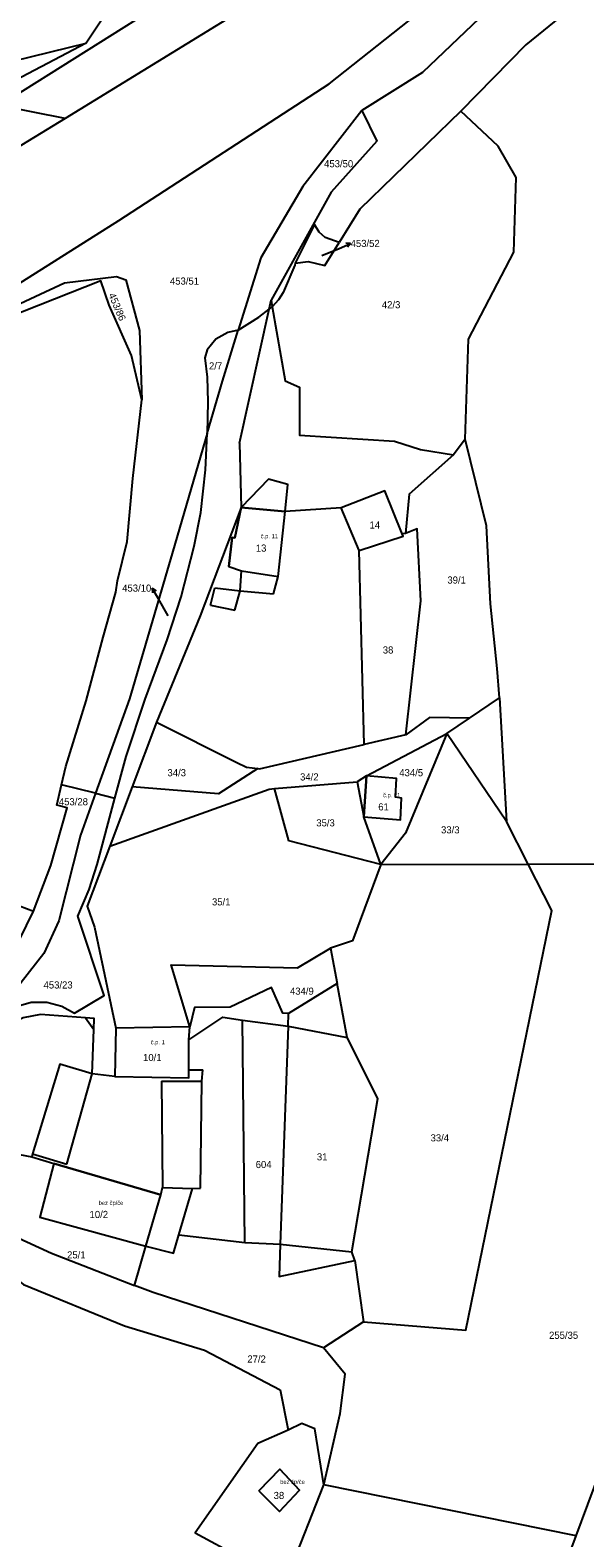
# Model space of a CAD drawing. Extents: x -882150 to -879379, y -1022570 to -1019819.
# Drawn here: x -880489.6 to -880356.9, y -1021365.7 to -1021005.3 of the extents above; entities that cross this region are included whole.
import ezdxf

# ---------------------------------------------------------------- set-up
doc = ezdxf.new("R2010")
doc.units = 0
for name, color, linetype in [('Definiční body', 7, 'Continuous'), ('Hranice parcel', 7, 'Continuous'), ('Parcelní čísla', 7, 'Continuous'), ('Polygon budovy', 7, 'Continuous'), ('Pop  PČ popisy', 7, 'Continuous'), ('Vnitřní kresba', 7, 'Continuous')]:
    doc.layers.add(name, color=color, linetype=linetype)

msp = doc.modelspace()

# ---------------------------------------------------------------- linework, layer by layer
at = {"layer": 'Hranice parcel'}
for p, q in [((-880476.16, -1021008.4), (-880502.57, -1021022.27)), ((-880481.22, -1021026.44), (-880495.95, -1021035.41)), ((-880431.99, -1021069.84), (-880431.71, -1021071.41)), ((-880385.56, -1021103.08), (-880388.33, -1021106.79)), ((-880415.23, -1021119.47), (-880428.61, -1021120.37)), ((-880410.9, -1021129.7), (-880415.23, -1021119.47)), ((-880399.83, -1021125.58), (-880400.61, -1021125.73)), ((-880409.7, -1021176.06), (-880410.9, -1021129.7)), ((-880459.41, -1021170.76), (-880465.21, -1021186.18)), ((-880389.96, -1021173.43), (-880384.55, -1021169.77)), ((-880399.71, -1021173.73), (-880409.7, -1021176.06)), ((-880409.15, -1021183.56), (-880389.96, -1021173.43)), ((-880431.14, -1021186.58), (-880411.38, -1021184.98)), ((-880409.15, -1021183.56), (-880411.38, -1021184.98)), ((-880411.38, -1021184.98), (-880409.82, -1021193.33)), ((-880473.96, -1021187.71), (-880482.08, -1021185.73)), ((-880473.96, -1021187.71), (-880469.31, -1021188.85)), ((-880465.21, -1021186.18), (-880470.56, -1021200.38)), ((-880427.72, -1021199.1), (-880431.14, -1021186.58)), ((-880405.75, -1021204.73), (-880409.82, -1021193.33)), ((-880405.75, -1021204.73), (-880427.72, -1021199.1)), ((-880405.75, -1021204.73), (-880370.46, -1021204.66)), ((-880370.46, -1021204.66), (-880352.16, -1021204.62)), ((-880497.26, -1021212.75), (-880488.78, -1021215.92)), ((-880417.76, -1021224.73), (-880416.19, -1021233.16)), ((-880416.19, -1021233.16), (-880427.78, -1021240.38)), ((-880438.79, -1021241.92), (-880427.85, -1021243.42)), ((-880427.85, -1021243.42), (-880427.78, -1021240.38)), ((-880469.09, -1021243.89), (-880469.32, -1021255.45)), ((-880451.42, -1021243.56), (-880469.09, -1021243.89)), ((-880469.32, -1021255.45), (-880474.8, -1021254.79)), ((-880496.75, -1021273.23), (-880489.23, -1021274.65)), ((-880464.66, -1021305.36), (-880461.94, -1021295.99)), ((-880411.95, -1021299.44), (-880409.86, -1021314.06)), ((-880409.86, -1021314.06), (-880419.42, -1021320.33)), ((-880428.51, -1021376.32), (-880419.38, -1021353.05)), ((-880359.04, -1021365.24), (-880419.38, -1021353.05))]:
    msp.add_line(p, q, dxfattribs=at)
for points in [[(-880199.05, -1020918.85), (-880200.75, -1020917.75), (-880202.77, -1020917.97), (-880233.19, -1020931.27), (-880251.05, -1020933.81), (-880268.87, -1020944.34), (-880277.99, -1020951.78), (-880283.59, -1020955.76), (-880289.65, -1020959.07), (-880309.25, -1020967.57), (-880323.7, -1020975.72), (-880346.68, -1020990.73), (-880361.3, -1021000.94), (-880371.02, -1021008.81), (-880386.57, -1021024.64)], [(-880309.24, -1020922.47), (-880346.3, -1020941.23), (-880393.91, -1020972.78), (-880481.22, -1021026.44)], [(-880469, -1020965.35), (-880470.29, -1020974.83), (-880471.2, -1020987.07), (-880471.46, -1020993.13), (-880470.95, -1020998.81), (-880470.95, -1021000.53), (-880476.16, -1021008.4)], [(-880574.71, -1021116.82), (-880511.95, -1021078.31), (-880468.39, -1021050.82), (-880418.11, -1021018.15), (-880374.5, -1020983.56)], [(-880374.5, -1020983.56), (-880382.21, -1021002.48), (-880395.74, -1021015.43), (-880410.24, -1021024.49)], [(-880511.24, -1021020.61), (-880502.88, -1021016.62), (-880493.44, -1021012.65), (-880476.16, -1021008.4)], [(-880481.22, -1021026.44), (-880497.01, -1021023.34), (-880502.57, -1021022.27)], [(-880410.24, -1021024.49), (-880424.37, -1021042.64), (-880434.46, -1021059.73), (-880439.82, -1021077.01)], [(-880410.24, -1021024.49), (-880406.66, -1021031.86), (-880417.64, -1021044.05), (-880431.99, -1021069.84)], [(-880386.57, -1021024.64), (-880410.77, -1021048.05), (-880415.69, -1021056.05)], [(-880385.56, -1021103.08), (-880384.77, -1021079.15), (-880373.92, -1021058.36), (-880373.35, -1021040.51), (-880377.69, -1021033.04), (-880386.57, -1021024.64)], [(-880415.69, -1021056.05), (-880419.02, -1021054.89), (-880420.51, -1021053.56), (-880421.57, -1021051.74), (-880426.2, -1021060.98)], [(-880426.2, -1021060.98), (-880423.12, -1021060.62), (-880419.08, -1021061.56), (-880415.69, -1021056.05)], [(-880426.2, -1021060.98), (-880426.26, -1021061.51), (-880429.07, -1021067.97), (-880430.23, -1021069.76), (-880431.71, -1021071.41)], [(-880519.8, -1021083.58), (-880502.52, -1021075.49), (-880481.4, -1021065.7), (-880468.96, -1021064.18), (-880466.73, -1021064.99), (-880463.43, -1021077.08), (-880462.9, -1021093.7)], [(-880462.9, -1021093.7), (-880465.35, -1021083.05), (-880470.69, -1021071.03), (-880472.67, -1021065.21), (-880498.73, -1021075.48), (-880519.8, -1021083.58)], [(-880439.82, -1021077.01), (-880434.91, -1021073.92), (-880432.47, -1021072), (-880431.71, -1021071.41)], [(-880431.71, -1021071.41), (-880428.58, -1021089.14), (-880425.15, -1021090.65), (-880425.18, -1021102.13), (-880402.46, -1021103.56), (-880396.21, -1021105.53), (-880388.33, -1021106.79)], [(-880439.82, -1021077.01), (-880442.34, -1021077.55), (-880445.16, -1021079.15), (-880447.28, -1021081.75), (-880447.85, -1021083.64), (-880447.23, -1021088.28), (-880447.11, -1021094.15), (-880447.26, -1021101.73)], [(-880447.26, -1021101.73), (-880443.6, -1021089.17), (-880439.82, -1021077.01)], [(-880482.08, -1021185.73), (-880481.03, -1021181.33), (-880476.2, -1021165.62), (-880472.17, -1021150.37), (-880469.07, -1021139.61), (-880468.72, -1021136.95), (-880466.42, -1021127.54), (-880465.02, -1021112.47), (-880462.9, -1021093.7)], [(-880447.26, -1021101.73), (-880456.01, -1021131.75), (-880465.87, -1021165.12), (-880473.96, -1021187.71)], [(-880469.31, -1021188.85), (-880466.62, -1021178.9), (-880462.07, -1021165.21), (-880456.8, -1021151.04), (-880453.51, -1021140.78), (-880450.35, -1021128.62), (-880448.81, -1021120.58), (-880447.63, -1021110.39), (-880447.26, -1021101.73)], [(-880384.55, -1021169.77), (-880377.35, -1021164.9), (-880377.91, -1021157.93), (-880379.53, -1021142.46), (-880380.44, -1021123.75), (-880385.56, -1021103.08)], [(-880388.33, -1021106.79), (-880398.93, -1021116.18), (-880399.83, -1021125.58)], [(-880428.61, -1021120.37), (-880427.96, -1021113.91), (-880432.6, -1021112.6), (-880439.14, -1021119.44)], [(-880400.61, -1021125.73), (-880404.76, -1021115.38), (-880415.23, -1021119.47)], [(-880439.14, -1021119.44), (-880448.93, -1021145.32), (-880459.41, -1021170.76)], [(-880410.9, -1021129.7), (-880400.41, -1021126.23), (-880400.61, -1021125.73)], [(-880399.71, -1021173.73), (-880396.15, -1021141.69), (-880397.02, -1021124.54), (-880399.83, -1021125.58)], [(-880459.41, -1021170.76), (-880440.17, -1021180.34), (-880437.84, -1021181.51), (-880435.12, -1021181.83)], [(-880384.55, -1021169.77), (-880394.06, -1021169.63), (-880399.71, -1021173.73)], [(-880389.96, -1021173.43), (-880399.79, -1021197.23), (-880405.75, -1021204.73)], [(-880370.46, -1021204.66), (-880375.65, -1021194.46), (-880389.96, -1021173.43)], [(-880435.12, -1021181.83), (-880434.73, -1021181.88), (-880409.7, -1021176.06)], [(-880435.12, -1021181.83), (-880444.54, -1021187.85), (-880465.21, -1021186.18)], [(-880409.82, -1021193.33), (-880401.02, -1021194.07), (-880400.8, -1021188.87), (-880402.24, -1021188.67), (-880401.94, -1021184.17), (-880409.15, -1021183.56)], [(-880518.44, -1021250.25), (-880514.62, -1021256.12), (-880507.85, -1021251.3), (-880501.52, -1021245.91), (-880496.1, -1021240.64), (-880492.92, -1021238.71), (-880489.34, -1021237.69), (-880485.62, -1021237.66), (-880482.02, -1021238.6), (-880479.01, -1021240.25), (-880471.89, -1021236.03), (-880478.16, -1021217.09), (-880475.5, -1021210.72), (-880473.54, -1021204.78), (-880469.31, -1021188.85)], [(-880473.96, -1021187.71), (-880477.55, -1021197.73), (-880482.75, -1021218.18), (-880486.35, -1021226.03), (-880491.71, -1021232.97), (-880502.05, -1021240.2), (-880503.97, -1021238.53)], [(-880488.78, -1021215.92), (-880484.66, -1021204.99), (-880480.78, -1021191.2), (-880483.25, -1021190.59), (-880482.08, -1021185.73)], [(-880470.56, -1021200.38), (-880432.45, -1021186.7), (-880431.14, -1021186.58)], [(-880470.56, -1021200.38), (-880475.94, -1021214.68), (-880474.23, -1021219.74), (-880469.09, -1021243.89)], [(-880405.75, -1021204.73), (-880412.54, -1021223.01), (-880417.76, -1021224.73)], [(-880409.86, -1021314.06), (-880385.39, -1021316.08), (-880364.8, -1021215.77), (-880370.46, -1021204.66)], [(-880359.04, -1021365.24), (-880347.89, -1021335.3), (-880343.04, -1021319.71), (-880341.7, -1021303.99), (-880342.38, -1021275.03), (-880352.4, -1021220.14), (-880352.16, -1021204.62)], [(-880503.97, -1021238.53), (-880497.17, -1021230.88), (-880492.15, -1021222.79), (-880488.78, -1021215.92)], [(-880451.42, -1021243.56), (-880455.83, -1021228.7), (-880425.68, -1021229.41), (-880417.76, -1021224.73)], [(-880427.78, -1021240.38), (-880429.16, -1021240.28), (-880431.84, -1021234.12), (-880441.77, -1021238.84), (-880450.27, -1021238.91), (-880451.42, -1021243.56)], [(-880411.95, -1021299.44), (-880412.64, -1021297.37), (-880406.45, -1021260.65), (-880413.79, -1021246.1), (-880416.19, -1021233.16)], [(-880474.8, -1021254.79), (-880474.36, -1021244.16), (-880474.25, -1021241.54), (-880476.39, -1021241.38), (-880487.08, -1021240.58), (-880491.24, -1021241.37), (-880501.78, -1021246.86)], [(-880469.32, -1021255.45), (-880451.67, -1021255.77), (-880451.67, -1021253.83), (-880451.67, -1021246.7), (-880443.48, -1021241.21), (-880438.79, -1021241.92)], [(-880461.94, -1021295.99), (-880455.35, -1021297.69), (-880454.03, -1021293.26), (-880438.23, -1021295.13), (-880438.79, -1021241.92)], [(-880427.85, -1021243.42), (-880429.8, -1021295.5), (-880430.05, -1021303.24), (-880411.95, -1021299.44)], [(-880474.8, -1021254.79), (-880482.51, -1021252.47), (-880489.01, -1021273.93), (-880489.23, -1021274.65)], [(-880529.31, -1021274.86), (-880506.49, -1021293.52), (-880491.17, -1021305.16), (-880467.02, -1021315.01), (-880447.92, -1021320.85), (-880429.84, -1021330.36), (-880427.85, -1021339.96)], [(-880489.23, -1021274.65), (-880483.89, -1021276.22), (-880487.28, -1021289.04), (-880477.92, -1021291.61), (-880461.94, -1021295.99)], [(-880493.37, -1021293.62), (-880484.47, -1021297.65), (-880464.66, -1021305.36)], [(-880419.42, -1021320.33), (-880460.21, -1021307.1), (-880464.66, -1021305.36)], [(-880419.38, -1021353.05), (-880415.46, -1021335.98), (-880414.29, -1021326.55), (-880419.42, -1021320.33)], [(-880427.85, -1021339.96), (-880435.17, -1021343.19), (-880450.1, -1021364.49), (-880439.53, -1021370.25)], [(-880419.38, -1021353.05), (-880421.48, -1021339.64), (-880424.64, -1021338.38), (-880427.85, -1021339.96)], [(-880403.27, -1021491.7), (-880402.77, -1021488.9), (-880394.62, -1021461.91), (-880369.65, -1021393.76), (-880359.04, -1021365.24)]]:
    msp.add_lwpolyline(points, dxfattribs=at)
at = {"layer": 'Polygon budovy'}
for points in [[(-880439.08, -1021134.58), (-880430.26, -1021135.92), (-880428.61, -1021120.37), (-880439.14, -1021119.44), (-880440.61, -1021126.62), (-880441.3, -1021126.54), (-880442.05, -1021133.53)], [(-880401.02, -1021194.07), (-880400.8, -1021188.87), (-880402.24, -1021188.67), (-880401.94, -1021184.17), (-880409.15, -1021183.56), (-880409.82, -1021193.33)], [(-880469.09, -1021243.89), (-880469.32, -1021255.45), (-880451.67, -1021255.77), (-880451.67, -1021253.83), (-880451.67, -1021246.7), (-880451.42, -1021243.56)], [(-880487.28, -1021289.04), (-880477.92, -1021291.61), (-880461.94, -1021295.99), (-880458.37, -1021283.7), (-880483.89, -1021276.22)], [(-880434.92, -1021354.49), (-880429.99, -1021359.38), (-880425.14, -1021354.33), (-880429.86, -1021349.26)]]:
    msp.add_lwpolyline(points, close=True, dxfattribs=at)
at = {"layer": 'Pop  PČ popisy'}
for p, q in [((-880419.8, -1021059.2), (-880415.71, -1021057.45)), ((-880415.71, -1021057.45), (-880412.948, -1021056.277)), ((-880412.948, -1021056.277), (-880414.065, -1021056.208)), ((-880412.948, -1021056.277), (-880413.674, -1021057.13)), ((-880458.92, -1021141.27), (-880460.42, -1021138.671)), ((-880460.42, -1021138.671), (-880459.486, -1021139.288)), ((-880460.42, -1021138.671), (-880460.353, -1021139.789)), ((-880456.6, -1021145.31), (-880458.92, -1021141.27))]:
    msp.add_line(p, q, dxfattribs=at)
at = {"layer": 'Vnitřní kresba'}
for p, q in [((-880497.01, -1021023.34), (-880353.65, -1020933.14)), ((-880432.47, -1021072), (-880431.99, -1021069.84)), ((-880439.51, -1021104.01), (-880432.47, -1021072)), ((-880439.51, -1021104.01), (-880439.14, -1021119.44)), ((-880440.61, -1021126.62), (-880439.14, -1021119.44)), ((-880439.14, -1021119.44), (-880428.61, -1021120.37)), ((-880430.26, -1021135.92), (-880428.61, -1021120.37)), ((-880442.05, -1021133.53), (-880441.3, -1021126.54)), ((-880441.3, -1021126.54), (-880440.61, -1021126.62)), ((-880442.05, -1021133.53), (-880439.08, -1021134.58)), ((-880439.38, -1021139.33), (-880439.08, -1021134.58)), ((-880439.08, -1021134.58), (-880430.26, -1021135.92)), ((-880446.5, -1021142.77), (-880445.43, -1021138.63)), ((-880445.43, -1021138.63), (-880439.38, -1021139.33)), ((-880431.37, -1021140.06), (-880430.26, -1021135.92)), ((-880440.61, -1021143.95), (-880439.38, -1021139.33)), ((-880439.38, -1021139.33), (-880431.37, -1021140.06)), ((-880446.5, -1021142.77), (-880440.61, -1021143.95)), ((-880377.35, -1021164.9), (-880375.65, -1021194.46)), ((-880409.82, -1021193.33), (-880409.15, -1021183.56)), ((-880476.39, -1021241.38), (-880474.36, -1021244.16)), ((-880451.67, -1021246.7), (-880451.42, -1021243.56)), ((-880427.85, -1021243.42), (-880413.79, -1021246.1)), ((-880451.67, -1021253.83), (-880448.33, -1021253.83)), ((-880448.5, -1021256.51), (-880448.33, -1021253.83)), ((-880480.82, -1021276.39), (-880474.8, -1021254.79)), ((-880458.19, -1021256.53), (-880457.95, -1021282)), ((-880458.19, -1021256.53), (-880453.4, -1021256.53)), ((-880453.4, -1021256.53), (-880448.5, -1021256.51)), ((-880448.87, -1021282.15), (-880448.5, -1021256.51)), ((-880489.01, -1021273.93), (-880480.82, -1021276.39)), ((-880483.89, -1021276.22), (-880458.37, -1021283.7)), ((-880458.37, -1021283.7), (-880457.95, -1021282)), ((-880457.95, -1021282), (-880450.75, -1021282.17)), ((-880454.03, -1021293.26), (-880450.75, -1021282.17)), ((-880450.75, -1021282.17), (-880448.87, -1021282.15)), ((-880461.94, -1021295.99), (-880458.37, -1021283.7)), ((-880438.23, -1021295.13), (-880429.8, -1021295.5)), ((-880429.8, -1021295.5), (-880412.64, -1021297.37)), ((-880434.92, -1021354.49), (-880429.86, -1021349.26)), ((-880429.86, -1021349.26), (-880425.14, -1021354.33)), ((-880434.92, -1021354.49), (-880429.99, -1021359.38)), ((-880429.99, -1021359.38), (-880425.14, -1021354.33))]:
    msp.add_line(p, q, dxfattribs=at)

# ---------------------------------------------------------------- texts
at = {"layer": 'Definiční body'}
for s, p in [('č.p. 11', (-880434.46, -1021126.76)), ('č.p. 21', (-880405.21, -1021188.67)), ('č.p. 1', (-880460.76, -1021247.72)), ('bez čp/če', (-880473.21, -1021286.14)), ('bez čp/če', (-880429.8, -1021352.83))]:
    msp.add_text(s, height=1, dxfattribs=at).set_placement(p)
at = {"layer": 'Parcelní čísla'}
for s, p in [('453/50', (-880419.29, -1021038.07)), ('453/52', (-880412.95, -1021057.12)), ('453/51', (-880456.16, -1021066.12)), ('42/3', (-880405.48, -1021071.78)), ('2/7', (-880446.82, -1021086.4)), ('14', (-880408.43, -1021124.44)), ('13', (-880435.62, -1021129.95)), ('453/10', (-880467.582, -1021139.52)), ('39/1', (-880389.81, -1021137.59)), ('38', (-880405.26, -1021154.31)), ('34/3', (-880456.75, -1021183.65)), ('434/5', (-880401.31, -1021183.64)), ('34/2', (-880425.04, -1021184.66)), ('453/28', (-880482.72, -1021190.59)), ('61', (-880406.34, -1021191.82)), ('35/3', (-880421.16, -1021195.64)), ('33/3', (-880391.33, -1021197.31)), ('35/1', (-880446.11, -1021214.53)), ('453/23', (-880486.39, -1021234.39)), ('434/9', (-880427.46, -1021235.87)), ('10/1', (-880462.59, -1021251.74)), ('33/4', (-880393.83, -1021270.94)), ('604', (-880435.65, -1021277.32)), ('31', (-880421.02, -1021275.48)), ('10/2', (-880475.38, -1021289.25)), ('25/1', (-880480.76, -1021298.92)), ('255/35', (-880365.49, -1021318.14)), ('27/2', (-880437.65, -1021323.81)), ('38', (-880431.36, -1021356.43))]:
    msp.add_text(s, height=1.7, dxfattribs=at).set_placement(p)
msp.add_text('453/86', height=1.7, rotation=293, dxfattribs=at).set_placement((-880470.898, -1021068.568))

doc.saveas('drawing.dxf')
